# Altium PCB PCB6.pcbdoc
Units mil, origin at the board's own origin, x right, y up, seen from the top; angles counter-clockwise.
Board outline 4829.93 x 4826.48 mil, 2 copper layers (Top Layer, Bottom Layer); 46 components, 40 nets, 167 pads, 42 vias.
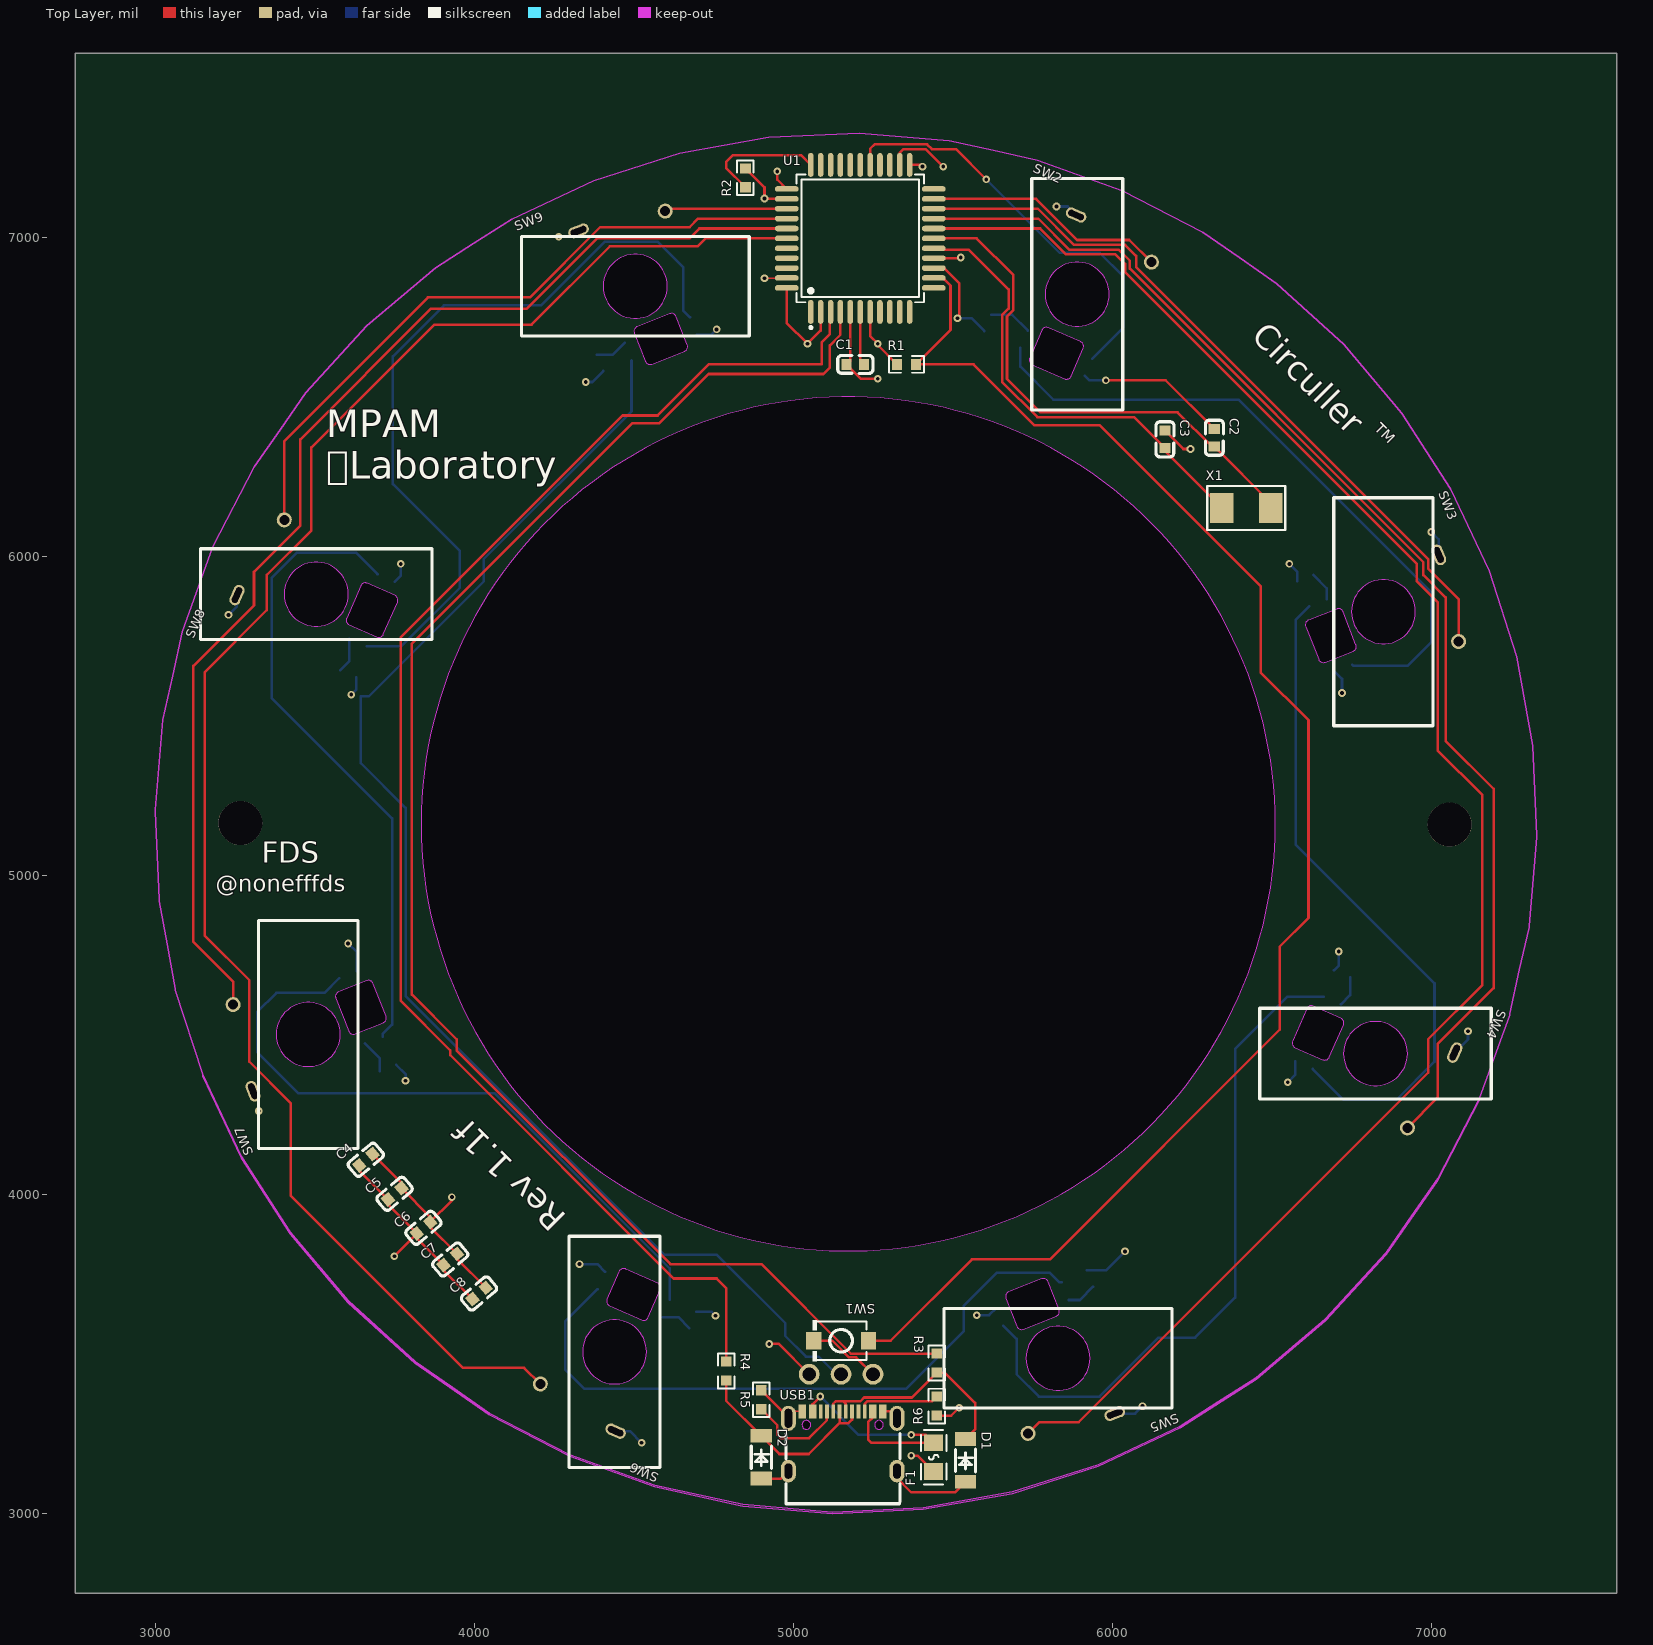
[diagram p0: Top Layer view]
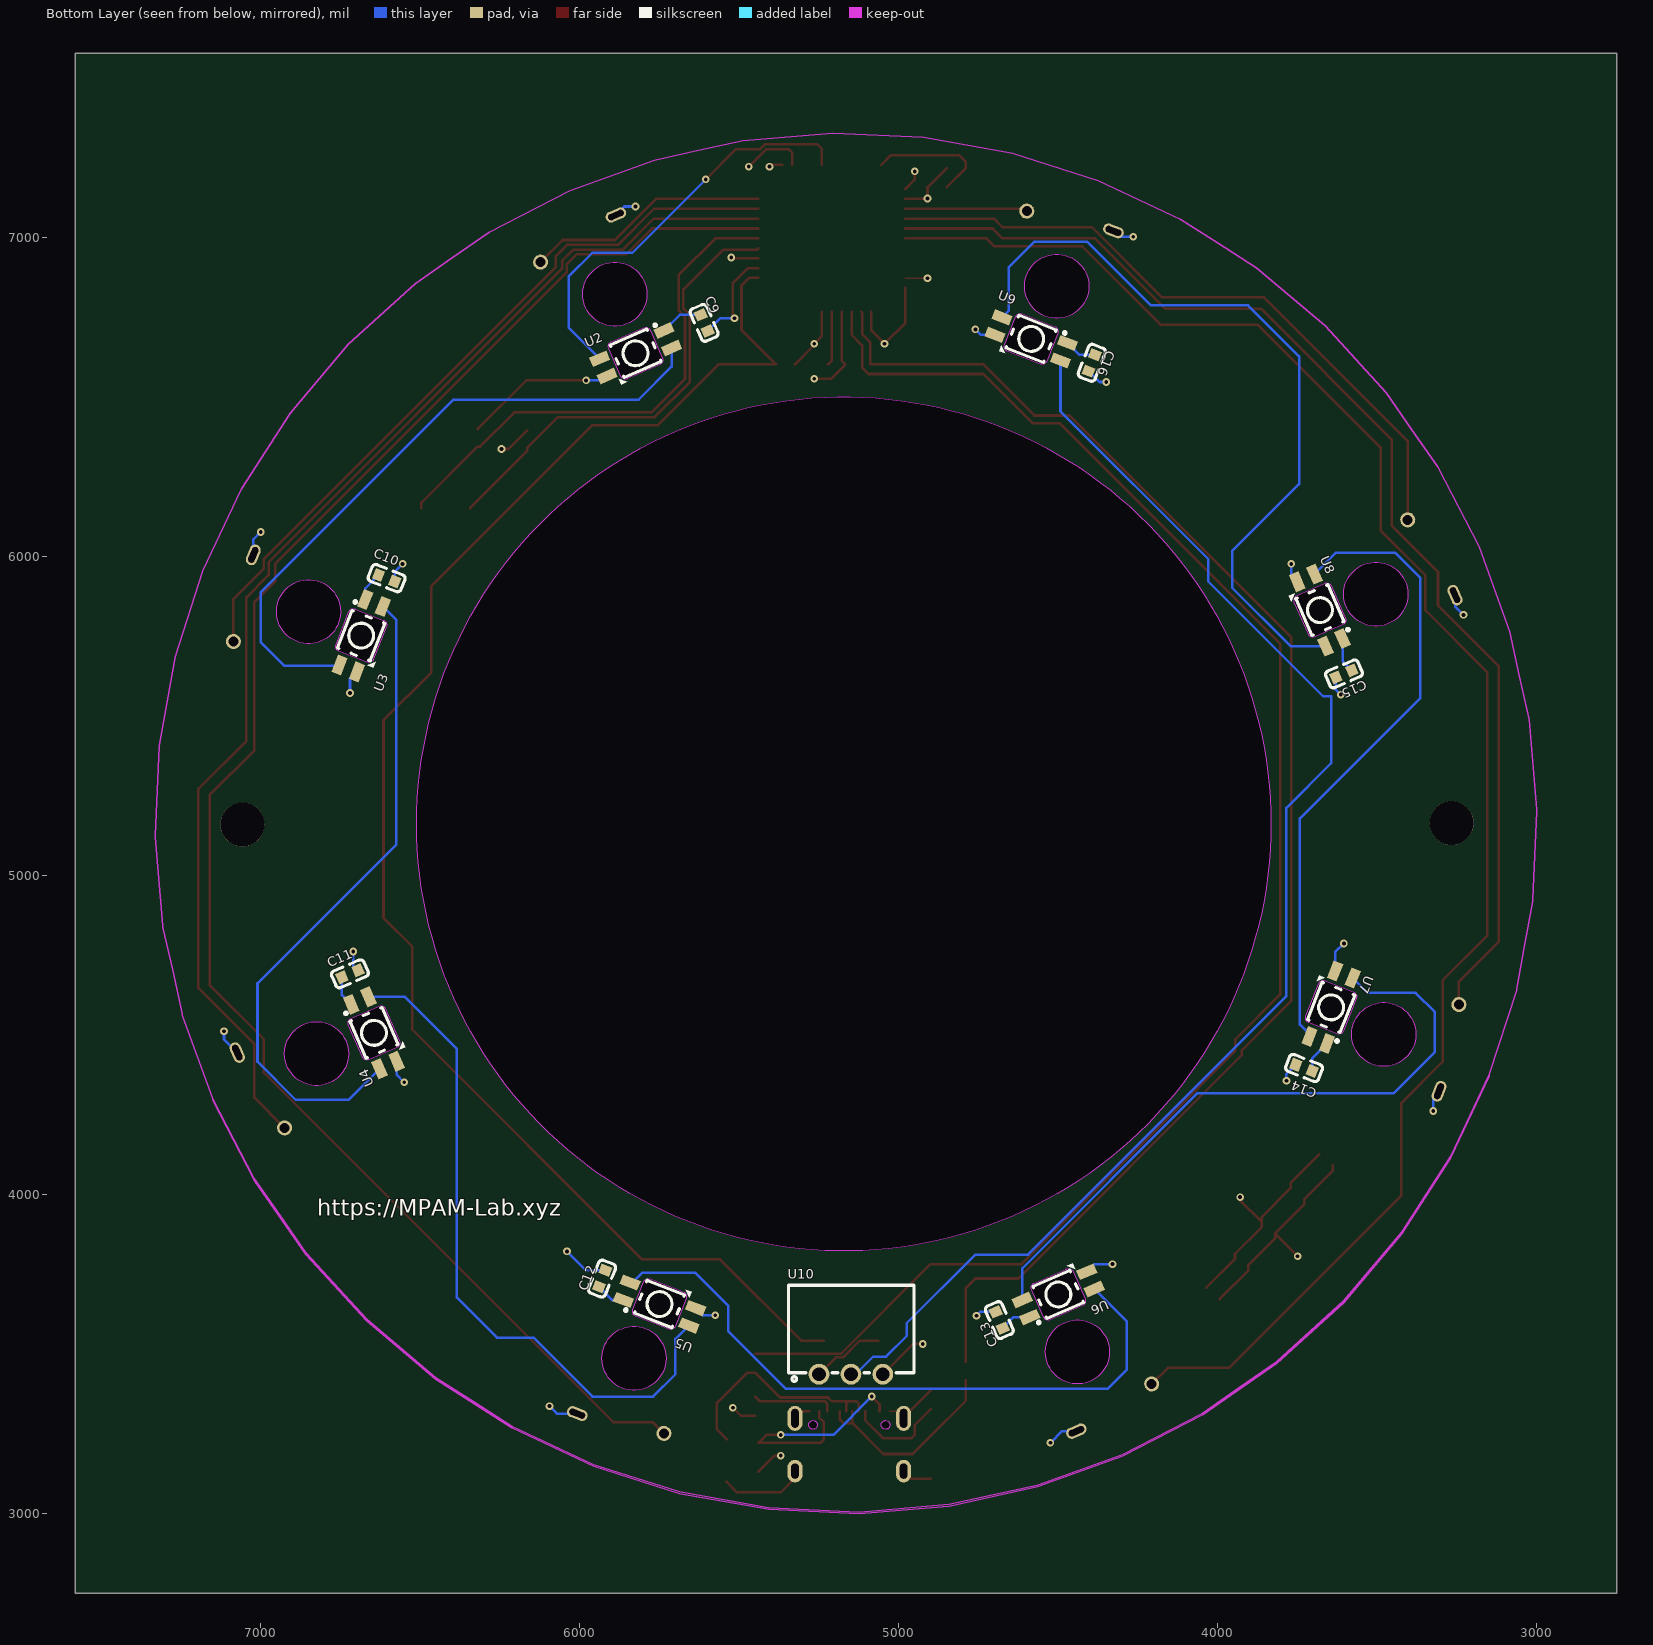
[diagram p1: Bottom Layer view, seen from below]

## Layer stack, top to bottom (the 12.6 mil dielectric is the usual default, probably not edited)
Top Layer: signal copper (thickness not stored)
Dielectric: dielectric 12.6, FR-4, Dk 4.8
Bottom Layer: signal copper (thickness not stored)

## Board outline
7579.93,2750 2750,2750 2750,7576.48 7579.93,7576.48
cut-out: 6510.41,5161.93 ccw(c5171.83,5161.93) 3833.24,5161.93 ccw(c5171.83,5161.93)

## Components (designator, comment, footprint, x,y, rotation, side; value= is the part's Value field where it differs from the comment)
C1 "CL10A105KB8NNNC" C0603 5194.52,6601.93 r0 top
C2 "CL10C220JB8NNNC" C0603 6319.52,6371.93 r270 top
C3 "CL10C220JB8NNNC" C0603 6164.52,6366.93 r270 top
C4 "CC0603KRX7R9BB104" C0603 3660.11,4109.3 r40.26 top
C5 "CC0603KRX7R9BB104" C0603 3750.42,4002.67 r40.26 top
C6 "CC0603KRX7R9BB104" C0603 3840.74,3896.03 r40.26 top
C7 "CC0603KRX7R9BB104" C0603 3924.76,3796.83 r40.26 top
C8 "CL10B474KA8NNNC" C0603 4015.07,3690.19 r40.26 top
C9 "CC0603KRX7R9BB104" C0603 5609.52,6731.93 r246.46 bottom
C10 "CC0603KRX7R9BB104" C0603 6604.52,5931.93 r201.46 bottom
C11 "CC0603KRX7R9BB104" C0603 6719.52,4691.93 r156.38 bottom
C12 "CC0603KRX7R9BB104" C0603 5929.52,3736.93 r111.38 bottom
C13 "CC0603KRX7R9BB104" C0603 4684.52,3606.93 r66.46 bottom
C14 "CC0603KRX7R9BB104" C0603 3729.52,4396.93 r21.46 bottom
C15 "CC0603KRX7R9BB104" C0603 3604.52,5631.93 r336.38 bottom
C16 "CC0603KRX7R9BB104" C0603 4394.52,6606.93 r291.38 bottom
D1 "ZMM3V6" LL-34_L3.5-W1.5-RD 5539.52,3166.93 r270 top
D2 "ZMM3V6" LL-34_L3.5-W1.5-RD 4899.52,3176.93 r270 top
F1 "2.5A/32VFUSESMD0805" F0805 5439.52,3176.93 r90 top
R1 "0603WAF1002T5E" R0603 5354.52,6601.93 r0 top
R2 "0603WAF1002T5E" R0603 4849.52,7186.93 r90 top
R3 "0603WAF220JT5E" R0603 5449.52,3471.93 r270 top
R4 "0603WAF220JT5E" R0603 4789.52,3446.93 r270 top
R5 "0603WAF5101T5E" R0603 4899.52,3356.93 r270 top
R6 "0603WAF5101T5E" R0603 5449.52,3336.93 r90 top
SW1 "TS-1088-AR02016" SW-SMD_L3.9-W3.0-P4.45 5149.52,3541.93 r180 top
SW2 "佳达隆矮轴_焊接" 佳达隆矮轴焊接#1 5889.52,6821.93 r336.46 top
SW3 "佳达隆矮轴_焊接" 佳达隆矮轴焊接#2 6849.52,5826.93 r291.46 top
SW4 "佳达隆矮轴_焊接" 佳达隆矮轴焊接#2 6824.52,4441.93 r246.38 top
SW5 "佳达隆矮轴_焊接" 佳达隆矮轴焊接#3 5829.52,3486.93 r201.38 top
SW6 "佳达隆矮轴_焊接" 佳达隆矮轴焊接#1 4439.52,3506.93 r156.46 top
SW7 "佳达隆矮轴_焊接" 佳达隆矮轴焊接#2 3479.52,4501.93 r111.46 top
SW8 "佳达隆矮轴_焊接" 佳达隆矮轴焊接#2 3504.52,5881.93 r66.38 top
SW9 "佳达隆矮轴_焊接" 佳达隆矮轴焊接#1 4504.52,6846.93 r21.38 top
U1 "ATMEGA32U4-AU" QFP-44_L10.0-W10.0-P0.80-LS13.2-BL 5209.52,6996.93 r0 top
U2 "WS2812B-3528幻彩反贴" LED-SMD_L3.2-W2.8-TR 5824.52,6636.93 r156.46 bottom
U3 "WS2812B-3528幻彩反贴" LED-SMD_L3.2-W2.8-TR 6684.52,5751.93 r111.46 bottom
U4 "WS2812B-3528幻彩反贴" LED-SMD_L3.2-W2.8-TR 6644.52,4506.93 r66.38 bottom
U5 "WS2812B-3528幻彩反贴" LED-SMD_L3.2-W2.8-TR 5749.52,3656.93 r21.38 bottom
U6 "WS2812B-3528幻彩反贴" LED-SMD_L3.2-W2.8-TR 4499.52,3686.93 r336.46 bottom
U7 "WS2812B-3528幻彩反贴" LED-SMD_L3.2-W2.8-TR 3644.52,4586.93 r291.46 bottom
U8 "WS2812B-3528幻彩反贴" LED-SMD_L3.2-W2.8-TR 3679.52,5831.93 r246.38 bottom
U9 "WS2812B-3528幻彩反贴" LED-SMD_L3.2-W2.8-TR 4584.52,6681.93 r201.38 bottom
U10 "XH2.54-WI-3P" CONN-TH_XH2.54-WI-3P 5149.52,3436.93 r180 bottom
USB1 "TYPE-C 16PIN 2MD(073)" USB-C-SMD_TYPE-C-6PIN-2MD-073 5154.52,3226.93 r0 top
X1 "XSHEELNANF-16MHZ" OSC-SMD_2P-L5.0-W3.2 6419.52,6151.93 r0 top

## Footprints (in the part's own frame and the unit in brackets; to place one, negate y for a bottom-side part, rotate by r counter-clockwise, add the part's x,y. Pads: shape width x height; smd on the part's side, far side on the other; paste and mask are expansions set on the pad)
C0603 [mm]
  rect 0.8x0.9 smd: 1(-0.7,0) 2(0.7,0)
  silkscreen extent -1.41,-0.71 1.39,0.72
CONN-TH_XH2.54-WI-3P [mm]
  round 1.65 hole 1.1: 1(-2.54,0) 2(0,0) 3(2.54,0)
  silkscreen extent -4.96,-0.56 5.02,7.09
F0805 [mm]
  rect 1.335x1.5 smd: 1(-1.142,0) 2(1.142,0)
  silkscreen extent -2.16,-1.02 2.16,1.02
LED-SMD_L3.2-W2.8-TR [mm]
  rect 1.5x0.82 smd: 1(2.8,0.75) 2(2.8,-0.75) 3(-2.8,-0.75) 4(-2.8,0.75)
  Multi-Layer board cut-out: 1.8,-1.2 1.746,-1.4 1.6,-1.547 1.4,-1.6 1.4,-1.6 1.4,-1.6 -1.4,-1.6 -1.403,-1.6 -1.406,-1.6 -1.406,-1.6 -1.604,-1.545 -1.747,-1.398 -1.8,-1.2 -1.8,-1.2 -1.8,-1.2 -1.8,-1.2 -1.8,-1.2 -1.8,-1.2 -1.8,1.2 -1.746,1.4 -1.6,1.546 -1.4,1.6 -1.4,1.6 1.4,1.6 1.4,1.6 1.6,1.547 1.746,1.4 1.8,1.2 1.8,1.2
  Multi-Layer keep-out region: 1.8,-1.2 1.746,-1.4 1.6,-1.547 1.4,-1.6 1.4,-1.6 1.4,-1.6 -1.4,-1.6 -1.403,-1.6 -1.406,-1.6 -1.406,-1.6 -1.604,-1.545 -1.747,-1.398 -1.8,-1.2 -1.8,-1.2 -1.8,-1.2 -1.8,-1.2 -1.8,-1.2 -1.8,-1.2 -1.8,1.2 -1.746,1.4 -1.6,1.546 -1.4,1.6 -1.4,1.6 1.4,1.6 1.4,1.6 1.6,1.547 1.746,1.4 1.8,1.2 1.8,1.2
  silkscreen extent -2.03,-1.83 2.42,1.52
LL-34_L3.5-W1.5-RD [mm]
  rect 1.1x1.7 smd: 1(-1.7,0) 2(1.7,0)
  silkscreen extent -0.9,-0.8 0.9,0.8
OSC-SMD_2P-L5.0-W3.2 [mm]
  rect 1.9x2.4 smd: 1(-1.95,0) 2(1.95,0)
  silkscreen extent -3.1,-1.75 3.1,1.75
QFP-44_L10.0-W10.0-P0.80-LS13.2-BL [mil]
  oval 17.36x74.62 smd: 1(-155,-230.37) 2(-124,-230.37) 3(-93,-230.37) 4(-62,-230.37) 5(-31,-230.37) 6(0,-230.37) 7(31,-230.37) 8(62,-230.37) 9(93,-230.37) 10(124,-230.37) 11(155,-230.37) 23(155,230.37) 24(124,230.37) 25(93,230.37) 26(62,230.37) 27(31,230.37) 28(0,230.37) 29(-31,230.37) 30(-62,230.37) 31(-93,230.37) 32(-124,230.37) 33(-155,230.37)
  oval 74.62x17.36 smd: 12(230.37,-155) 13(230.37,-124) 14(230.37,-93) 15(230.37,-62) 16(230.37,-31) 17(230.37,0) 18(230.37,31) 19(230.37,62) 20(230.37,93) 21(230.37,124) 22(230.37,155) 34(-230.37,155) 35(-230.37,124) 36(-230.37,93) 37(-230.37,62) 38(-230.37,31) 39(-230.37,0) 40(-230.37,-31) 41(-230.37,-62) 42(-230.37,-93) 43(-230.37,-124) 44(-230.37,-155)
  silkscreen extent -200,-283 200,200
R0603 [mil]
  rect 31.75x34.02 smd: 1(-29.66,0) 2(29.66,0)
  silkscreen extent -55,-26 55,26
SW-SMD_L3.9-W3.0-P4.45 [mm]
  rect 1.23x1.36 smd: 1(-2.185,0) 2(2.185,0)
  silkscreen extent -2.03,-1.62 2.25,1.62
USB-C-SMD_TYPE-C-6PIN-2MD-073 [mm]
  rect 0.6x1.1 smd: 1(-3.2,2.375) 2(-2.4,2.375) 11(2.4,2.375) 12(3.2,2.375)
  rect 0.3x1.1 smd: 3(-1.75,2.375) 4(-1.25,2.375) 5(-0.75,2.375) 6(-0.25,2.375) 7(0.25,2.375) 8(0.75,2.375) 9(1.25,2.375) 10(1.75,2.375)
  oval 1.2x1.8 hole 0.6 slot 1.2 at 90 deg: 13(-4.325,-2.375) 14(4.325,-2.375)
  oval 1.2x2 hole 0.6 slot 1.5 at 90 deg: 13(-4.325,1.825) 14(4.325,1.825)
  Multi-Layer board cut-out: -2.54,1.305 -2.575,1.457 -2.672,1.579 -2.812,1.646 -2.968,1.646 -3.108,1.579 -3.205,1.457 -3.24,1.305 -3.24,1.305 -3.205,1.153 -3.108,1.031 -2.968,0.964 -2.812,0.964 -2.672,1.031 -2.575,1.153 -2.54,1.305
  Multi-Layer board cut-out: 3.24,1.305 3.205,1.457 3.108,1.579 2.968,1.646 2.812,1.646 2.672,1.579 2.575,1.457 2.54,1.305 2.54,1.305 2.575,1.153 2.672,1.031 2.812,0.964 2.968,0.964 3.108,1.031 3.205,1.153 3.24,1.305
  Multi-Layer keep-out region: -2.54,1.305 -2.575,1.457 -2.672,1.579 -2.812,1.646 -2.968,1.646 -3.108,1.579 -3.205,1.457 -3.24,1.305 -3.24,1.305 -3.205,1.153 -3.108,1.031 -2.968,0.964 -2.812,0.964 -2.672,1.031 -2.575,1.153 -2.54,1.305
  Multi-Layer keep-out region: 3.24,1.305 3.205,1.457 3.108,1.579 2.968,1.646 2.812,1.646 2.672,1.579 2.575,1.457 2.54,1.305 2.54,1.305 2.575,1.153 2.672,1.031 2.812,0.964 2.968,0.964 3.108,1.031 3.205,1.153 3.24,1.305
  silkscreen extent -4.5,-4.97 4.57,0.6
佳达隆矮轴焊接#1 [mm]
  oval 1.7x0.9 hole 0.5 slot 1.3 at 0 deg: 1(-2.6,5.75)
  round 1.2 hole 0.8: 2(4.4,4.7)
  Multi-Layer board cut-out: 2.338,1.019 1.664,1.932 0.661,2.463 -0.473,2.506 -1.513,2.053 -2.254,1.193 -2.548,0.097 -2.338,-1.019 -2.338,-1.019 -1.664,-1.932 -0.661,-2.463 0.473,-2.506 1.513,-2.053 2.254,-1.193 2.548,-0.097 2.338,1.019
  Multi-Layer keep-out region: 2.338,1.019 1.664,1.932 0.661,2.463 -0.473,2.506 -1.513,2.053 -2.254,1.193 -2.548,0.097 -2.338,-1.019 -2.338,-1.019 -1.664,-1.932 -0.661,-2.463 0.473,-2.506 1.513,-2.053 2.254,-1.193 2.548,-0.097 2.338,1.019
  silkscreen extent -7,-9.89 7,9.89
佳达隆矮轴焊接#2 [mm]
  oval 1.7x0.9 hole 0.5 slot 1.3 at 0 deg: 1(-2.6,5.75)
  round 1.2 hole 0.8: 2(4.4,4.7)
  Multi-Layer board cut-out: 0.933,2.373 -0.189,2.543 -1.274,2.209 -2.106,1.437 -2.521,0.381 -2.437,-0.75 -1.87,-1.734 -0.933,-2.373 -0.933,-2.373 0.189,-2.543 1.274,-2.209 2.106,-1.437 2.521,-0.381 2.437,0.75 1.87,1.734 0.933,2.373
  Multi-Layer keep-out region: 0.933,2.373 -0.189,2.543 -1.274,2.209 -2.106,1.437 -2.521,0.381 -2.437,-0.75 -1.87,-1.734 -0.933,-2.373 -0.933,-2.373 0.189,-2.543 1.274,-2.209 2.106,-1.437 2.521,-0.381 2.437,0.75 1.87,1.734 0.933,2.373
  silkscreen extent -9.89,-7 9.89,7
佳达隆矮轴焊接#3 [mm]
  oval 1.7x0.9 hole 0.5 slot 1.3 at 180 deg: 1(-2.6,5.75)
  round 1.2 hole 0.8: 2(4.4,4.7)
  Multi-Layer board cut-out: -2.375,0.93 -2.543,-0.193 -2.207,-1.277 -1.435,-2.108 -0.378,-2.522 0.754,-2.436 1.736,-1.868 2.375,-0.93 2.375,-0.93 2.543,0.193 2.207,1.277 1.435,2.108 0.378,2.522 -0.754,2.436 -1.736,1.868 -2.375,0.93
  Multi-Layer keep-out region: -2.375,0.93 -2.543,-0.193 -2.207,-1.277 -1.435,-2.108 -0.378,-2.522 0.754,-2.436 1.736,-1.868 2.375,-0.93 2.375,-0.93 2.543,0.193 2.207,1.277 1.435,2.108 0.378,2.522 -0.754,2.436 -1.736,1.868 -2.375,0.93
  silkscreen extent -9.89,-7 9.89,7

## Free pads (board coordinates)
  round 137.8 hole 137.8 unplated: 13(3266.83,5164.52)
  round 137.8 hole 137.8: 14(7056.83,5159.52)

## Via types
v1: diameter 24.02, hole 12.01, Top Layer to Bottom Layer, 42 vias

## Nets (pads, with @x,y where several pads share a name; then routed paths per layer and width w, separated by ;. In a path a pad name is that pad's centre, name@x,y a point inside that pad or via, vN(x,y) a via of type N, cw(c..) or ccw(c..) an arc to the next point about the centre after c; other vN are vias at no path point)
1: SW9.2 U1.36 | length 383.9
  Top Layer w7.99: SW9.2 4605.91,7089.93 U1.36
2: SW5.2 U1.18 | length 5437
  Top Layer w7.99: U1.18 5773.52,7027.93 5854.52,6946.93 6009.52,6946.93 6039.52,6916.93 6039.52,6891.93 6954.52,5976.93 6954.52,5921.93 7019.52,5856.93 7019.52,5391.93 7159.52,5251.93 7159.52,4656.93 6989.52,4486.93 6989.52,4381.93 5894.52,3286.93 5771.12,3286.93 SW5.2
3: SW2.2 U1.21 | length 764.6
  Top Layer w7.99: U1.21 5760.52,7120.93 5889.52,6991.93 6052.68,6991.93 SW2.2
4: SW6.2 U1.39 | length 5383.4
  Top Layer w7.99: SW6.2 4156.35,3456.93 3964.52,3456.93 3424.52,3996.93 3424.52,4286.93 3294.52,4416.93 3294.52,4671.93 3154.52,4811.93 3154.52,5636.93 3349.52,5831.93 3349.52,5941.93 3489.52,6081.93 3489.52,6341.93 3874.52,6726.93 4179.52,6726.93 4424.52,6971.93 4699.52,6971.93 4724.52,6996.93 U1.39
5: SW3.2 U1.20 | length 2323.1
  Top Layer w7.99: U1.20 5766.52,7089.93 5879.52,6976.93 6039.52,6976.93 6074.52,6941.93 6074.52,6906.93 6989.52,5991.93 6989.52,5961.93 7085.1,5866.35 SW3.2
6: SW7.2 U1.38 | length 3760.2
  Top Layer w7.99: SW7.2 3243.94,4667.51 3119.52,4791.93 3119.52,5656.93 3309.52,5846.93 3309.52,5951.93 3454.52,6096.93 3454.52,6366.93 3864.52,6776.93 4164.52,6776.93 4384.52,6996.93 4674.52,6996.93 4705.52,7027.93 U1.38
7: SW4.2 U1.19 | length 3971.2
  Top Layer w7.99: U1.19 5767.52,7058.93 5864.52,6961.93 6019.52,6961.93 6054.52,6926.93 6054.52,6901.93 6974.52,5981.93 6974.52,5941.93 7044.52,5871.93 7044.52,5421.93 7194.52,5271.93 7194.52,4646.93 7019.52,4471.93 7019.52,4303.95 SW4.2
8: SW8.2 U1.37 | length 2110.5
  Top Layer w7.99: SW8.2 3404.4,6361.81 3854.52,6811.93 4174.52,6811.93 4394.52,7031.93 4674.52,7031.93 4701.52,7058.93 U1.37
$1N992: C2.2 U1.17 X1.2 | length 1634.3
  Top Layer w7.99: U1.17 5574.52,6996.93 5689.52,6881.93 5689.52,6771.93 5669.52,6751.93 5669.52,6556.93 5774.52,6451.93 6204.52,6451.93 6312.08,6344.37 C2.2 6496.29,6167.6 X1.2
$1N1040: C3.2 U1.16 X1.1 | length 1443.6
  Top Layer w7.99: U1.16 5443.89,6961.93 5549.52,6961.93 5674.52,6836.93 5674.52,6776.93 5654.52,6756.93 5654.52,6546.93 5764.52,6436.93 6066.96,6436.93 C3.2 6164.52,6330.16 X1.1
$1N1214: R1.2 SW1.1 U1.13 | length 4904.9
  Top Layer w7.99: SW1.1 5304.52,3541.93 5559.52,3796.93 5804.52,3796.93 6524.52,4516.93 6524.52,4776.93 6614.52,4866.93 6614.52,5486.93 6464.52,5636.93 6464.52,5906.93 5959.52,6411.93 5754.52,6411.93 5564.52,6601.93 R1.2 5492.51,6710.26 5492.51,6848.93 5468.52,6872.93 U1.13
$1N1318: R2.1 U1.33 | length 390.1
  Top Layer w7.99: R2.1 4789.52,7217.27 4789.52,7236.93 4809.52,7256.93 5024.89,7256.93 U1.33
$1N2823: F1.2 USB1.2 USB1.11 | length 775.4
  Top Layer w7.99: USB1.2 5060.03,3342.44 v1(5084.52,3366.93) ; USB1.11 5249.01,3301.42 5234.52,3286.93 5234.52,3231.93 5244.54,3221.91 F1.2 5414.5,3246.93 v1(5369.52,3246.93)
  Bottom Layer w7.99: v1(5084.52,3366.93) 5204.52,3246.93 v1(5369.52,3246.93)
$1N3423: D1.1 R3.2 USB1.5 USB1.7 | length 709
  Top Layer w7.99: USB1.5 5124.99,3344.39 5132.68,3352.08 5156.37,3352.08 ; USB1.7 5164.36,3344.09 5156.37,3352.08 ; D1.1 5569.52,3263.86 5569.52,3346.93 5474.18,3442.27 R3.2 5371.33,3364.08 5221.67,3364.08 5209.67,3352.08 5156.37,3352.08
$1N3438: D2.1 R4.2 USB1.6 USB1.8 | length 634.4
  Top Layer w7.99: R4.2 4789.52,3353.86 D2.1 4956.45,3186.93 5048.18,3186.93 5144.67,3283.43 ; USB1.6 5144.67,3283.43 ; USB1.8 5184.04,3294.78 5172.68,3283.43 5144.67,3283.43
$1N3472: R5.2 USB1.4 | length 311.8
  Top Layer w7.99: R5.2 4949.52,3277.27 4949.52,3246.93 4959.52,3236.93 5049.52,3236.93 5105.31,3292.72 USB1.4
$1N3479: R6.2 USB1.10 | length 259.1
  Top Layer w7.99: USB1.10 5223.42,3344.09 5231.41,3352.08 5435.01,3352.08 R6.2
$1N3933: U2.2 U3.4 | length 2074.7
  Bottom Layer w7.99: U2.2 5711.66,6594.79 5814.52,6491.93 6394.52,6491.93 6999.52,5886.93 6999.52,5731.93 6924.52,5656.93 6755.52,5656.93 U3.4
$1N3938: U3.2 U4.4 | length 2096.5
  Bottom Layer w7.99: U3.2 6574.52,5801.53 6574.52,5096.93 7009.52,4661.93 7009.52,4416.93 6889.52,4296.93 6724.56,4296.93 U4.4
$1N3943: U4.2 U5.4 | length 2136.6
  Bottom Layer w7.99: U5.4 5699.52,3547.35 5699.52,3436.93 5769.52,3366.93 5959.52,3366.93 6144.52,3551.93 6259.52,3551.93 6384.52,3676.93 6384.52,4456.93 6547.35,4619.76 U4.2
$1N3948: U5.2 U6.4 | length 2086.3
  Bottom Layer w7.99: U6.4 4284.52,3601.75 4284.52,3451.93 4345.71,3390.74 5353.33,3390.74 5534.52,3571.93 5534.52,3651.93 5637,3754.41 5804.03,3754.41 5833.82,3724.61 U5.2
$1N3953: U6.2 U7.4 | length 2099.2
  Bottom Layer w7.99: U7.4 3529.91,4631.93 3379.52,4631.93 3319.52,4571.93 3319.52,4446.93 3449.52,4316.93 4064.52,4316.93 4612.38,3769.07 U6.2
$1N3959: U7.2 U8.4 | length 1998.6
  Bottom Layer w7.99: U8.4 3629.47,6011.93 3444.52,6011.93 3364.52,5931.93 3364.52,5556.93 3742.14,5179.3 3742.14,4532.51 3712.32,4502.69 U7.2
$1N3965: U8.2 U9.4 | length 2438.5
  Bottom Layer w7.99: U8.2 3771.68,5719.09 3954.52,5901.93 3954.52,6016.93 3744.52,6226.93 3744.52,6626.93 3904.52,6786.93 4209.52,6786.93 4409.52,6986.93 4574.52,6986.93 4654.52,6906.93 4654.52,6771.5 U9.4
$1N4279: C9.1 U2.1 | length 135.1
  Bottom Layer w7.99: C9.1 5686.09,6757.19 U2.1
$1N4296: C10.1 U3.1 | length 93.9
  Bottom Layer w7.99: C10.1 6671.68,5900.5 U3.1
$1N4306: C11.1 U4.1 | length 96.8
  Bottom Layer w7.99: U4.1 6744.77,4625.12 C11.1
$1N4316: C12.1 U5.1 | length 93.9
  Bottom Layer w7.99: U5.1 5897.92,3669.62 C12.1
$1N4320: C13.1 U6.1 | length 98.9
  Bottom Layer w7.99: U6.1 4639.35,3615.82 C13.1
$1N4353: C16.1 U9.1 | length 101.8
  Bottom Layer w7.99: C16.1 4434.45,6632.59 U9.1
$1N4416: C14.1 U7.1 | length 105.9
  Bottom Layer w7.99: U7.1 3703.87,4427.02 C14.1
$1N4551: C15.1 U8.1 | length 111.8
  Bottom Layer w7.99: C15.1 3608.29,5671.99 U8.1
$1N4867: C1.2 U1.6 | length 169.8
  Top Layer w7.99: U1.6 5209.52,6614.49 C1.2
D+: R4.1 U1.3 | length 4621.9
  Top Layer w7.99: R4.1 4789.52,3706.93 4759.52,3736.93 4624.52,3736.93 3924.52,4436.93 3924.52,4451.93 3769.52,4606.93 3769.52,5746.93 4464.52,6441.93 4574.52,6441.93 4734.52,6601.93 5089.52,6601.93 5089.52,6671.93 5114.52,6696.93 5114.52,6764.56 U1.3
D-: R3.1 U1.4 | length 5088.2
  Top Layer w7.99: U1.4 5147.52,6694.93 5114.52,6661.93 5114.52,6591.93 5094.52,6571.93 4734.52,6571.93 4579.52,6416.93 4494.52,6416.93 3804.52,5726.93 3804.52,4626.93 3944.52,4486.93 3944.52,4451.93 4614.52,3781.93 4899.52,3781.93 5179.86,3501.59 R3.1
DOUT: U9.2 U10.2 | length 4295.5
  Bottom Layer w7.99: U9.2 4492.63,6455.04 4029.52,5991.93 4029.52,5921.93 3669.52,5561.93 3644.52,5561.93 3644.52,5351.93 3784.52,5211.93 3784.52,4621.93 4594.52,3811.93 4759.52,3811.93 4974.52,3596.93 4974.52,3556.93 5039.52,3491.93 5079.52,3491.93 5134.52,3436.93 U10.2
GND: C1.1 C2.1 C3.1 C4.1 C5.1 C6.1 C7.1 C8.1 D1.2 D2.2 R2.2 R5.1 R6.1 SW1.2 SW2.1 SW3.1 SW4.1 SW5.1 SW6.1 SW7.1 SW8.1 SW9.1 U1.5 U1.15 U1.23 U1.35 U1.43 U2.3 U3.3 U4.3 U5.3 U6.3 U7.3 U8.3 U9.3 U10.1 USB1.1 USB1.12 USB1.13 USB1.14 | length 4007.4
  Top Layer w5: v1(4909.52,6871.93) 4978.15,6871.93 U1.43 ; USB1.13@4984.24,3298.78 5005.89,3320.43 USB1.1
  Top Layer w7.99: C4.1 3639.07,4075.17 C5.1 3729.39,3968.53 C6.1 ; v1(3749.52,3806.93) 3749.52,3808.03 C6.1 ; C8.1 3903.72,3762.69 C7.1 3819.71,3863.03 C6.1 ; R2.2 4909.52,7156.59 v1(4909.52,7121.93) 4910.52,7120.93 U1.35 ; D2.2 4960.82,3110 USB1.13@4984.24,3133.42 ; R5.1 4984.24,3301.86 USB1.13@4984.24,3298.78 ; SW1.2 5122.54,3541.93 5174.88,3489.58 5196.87,3489.58 U10.1 ; U1.5 5178.52,6613.49 C1.1 5211.96,6556.93 v1(5264.52,6556.93) ; USB1.12 5303.14,3320.43 USB1.14@5324.79,3298.78 ; USB1.14@5324.79,3133.42 5324.79,3111.65 5369.52,3066.93 5506.45,3066.93 D1.2 ; U1.23 5399.15,7227.3 v1(5404.52,7221.93) ; U1.15 5522.52,6934.93 v1(5524.52,6936.93) ; R6.1 5494.86,3307.27 v1(5519.52,3331.93) ; v1(5979.52,6551.93) 6167.08,6551.93 C2.1 ; C3.1 6222.08,6336.93 v1(6244.52,6336.93)
  Bottom Layer w7.99: v1(3229.52,5816.93) 3256.09,5843.5 SW8.1 ; SW7.1 3324.52,4305.61 v1(3324.52,4261.93) ; v1(3604.52,4786.93) 3631.68,4759.77 U7.3 ; U8.3 3769.52,5939.87 v1(3769.52,5976.93) ; v1(4264.52,7001.93) 4308.19,7001.93 SW9.1 ; v1(4329.52,3781.93) 4386.35,3781.93 U6.3 ; SW6.1 4487.94,3258.51 v1(4524.52,3221.93) ; U9.3 4742.21,6694.62 v1(4759.52,6711.93) ; v1(5574.52,3621.93) 5613.79,3621.93 U5.3 ; v1(5824.52,7096.93) 5859.52,7096.93 SW2.1 ; U2.3 5927.68,6551.93 v1(5979.52,6551.93) ; SW5.1 6071.04,3313.45 v1(6094.52,3336.93) ; v1(6549.52,4351.93) 6573.29,4375.7 U4.3 ; U3.3 6719.52,5616.37 v1(6719.52,5571.93) ; v1(6999.52,6076.93) 7022.77,6053.68 SW3.1 ; SW4.1 7114.52,4486.57 v1(7114.52,4511.93)
LED: U1.27 U2.4 | length 1319.5
  Top Layer w7.99: U1.27 5240.52,7277.93 5254.52,7291.93 5419.52,7291.93 5434.52,7276.93 5509.52,7276.93 v1(5604.52,7181.93)
  Bottom Layer w7.99: v1(5604.52,7181.93) 5834.52,6951.93 5959.52,6951.93 6034.52,6876.93 6034.52,6717.11 U2.4
VCC: C4.2 C5.2 C6.2 C7.2 C8.2 C9.2 C10.2 C11.2 C12.2 C13.2 C14.2 C15.2 C16.2 F1.1 R1.1 U1.2 U1.7 U1.14 U1.24 U1.34 U1.44 U10.3 | length 2559.1
  Top Layer w7.99: C4.2 3771.45,4036.8 C5.2 3861.77,3930.16 C6.2 ; v1(3929.61,3991.93) 3929.61,3981.68 C6.2 ; C8.2 3945.79,3798.32 C7.2 3861.77,3898.66 C6.2 ; v1(4924.52,3531.93) 4954.52,3531.93 U10.3 ; v1(4949.52,7206.93) 4949.52,7181.56 U1.34 ; U1.44 4979.15,6732.3 v1(5044.52,6666.93) 5085.52,6707.93 U1.2 ; U1.7 5240.52,6690.93 v1(5264.52,6666.93) 5264.52,6662.27 R1.1 ; U1.24 5333.52,7265.93 5344.52,7276.93 5414.52,7276.93 v1(5469.52,7221.93) ; v1(5369.52,3181.93) 5389.54,3181.93 F1.1 ; U1.14 5472.52,6903.93 5519.52,6856.93 5519.52,6751.93 v1(5514.52,6746.93)
  Bottom Layer w7.99: v1(3614.52,5566.93) 3629.77,5582.18 C15.2 ; C14.2 3784.52,4377.66 v1(3784.52,4356.93) ; v1(4349.52,6546.93) 4370.23,6546.93 C16.2 ; C13.2 4744.24,3632.19 v1(4756.12,3620.32) ; v1(5514.52,6746.93) 5558.24,6746.93 C9.2 ; C12.2 5980.18,3762.59 v1(6039.52,3821.93) ; v1(6554.52,5976.93) 6578.87,5952.58 C10.2 ; C11.2 6709.52,4718.22 v1(6709.52,4761.93)
"": pad.13 pad.14 U1.1 U1.8 U1.9 U1.10 U1.11 U1.12 U1.22 U1.25 U1.26 U1.28 U1.29 U1.30 U1.31 U1.32 U1.40 U1.41 U1.42 USB1.3 USB1.9

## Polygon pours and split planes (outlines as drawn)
GND on GND (split plane): 5405.87,3028.1 5124.25,3015 4843.34,3038.7 4705.63,3068.75 4567.92,3098.8 4302.72,3194.26 4052.28,3323.46 3936.58,3403.81 3820.87,3484.17 3612.47,3673.66 3430.62,3888.67 3354.54,4007.1 3278.46,4125.53 3158.56,4380.22 3073.28,4642.57 3073.28,4645.86 ccw(c3072.48,4646.68) 3073.12,4647.64 3048.12,4786.77 ccw(c3047.18,4786.61) 3048.12,4786.8 ccw(c3047.17,4786.64) 3048.11,4786.83 3023.28,4920.16 3023.28,4924.11 ccw(c3022.29,4924.33) 3023.27,4924.59 3010.1,5201.86 3010.1,5206.08 3033.87,5486.68 3063.97,5624.12 3094.08,5761.56 3189.72,6026.24 3319.16,6276.2 3399.68,6391.68 3480.19,6507.16 3670.04,6715.17 3885.47,6896.66 4004.13,6972.6 4122.79,7048.54 4377.94,7168.2 4646.57,7253.59 4785.31,7278.43 4924.06,7303.27 5205.67,7316.36 5486.59,7292.66 5624.3,7262.61 5762,7232.56 6027.2,7137.1 6277.65,7007.91 6393.35,6927.55 6509.05,6847.19 6717.46,6657.71 6899.3,6442.69 6975.39,6324.26 7051.47,6205.83 7171.36,5951.17 7256.92,5683.07 7281.8,5544.59 7306.69,5406.12 7319.83,5124.62 7319.83,5120.41 7296,4844.04 ccw(c7296.93,4843.56) 7295.97,4843.17 7295.97,4839.42 7265.97,4707.32 ccw(c7266.9,4707.09) 7265.96,4707.28 ccw(c7266.89,4707.05) 7265.95,4707.24 7235.71,4569.16 ccw(c7236.17,4568.01) 7235.47,4566.99 7235.47,4563.91 7140.22,4305.15 7010.76,4055.16 6930.25,3939.68 6849.74,3824.2 6659.89,3616.2 6444.46,3434.7 6325.8,3358.76 6207.14,3282.83 5951.98,3163.17 5683.36,3077.77 5544.62,3052.93
GND on GND (split plane): 3258.1,5883.44 3283.67,5872.25 3279.67,5863.09 3254.09,5874.27
GND on GND (split plane): 3232.52,5894.62 3258.1,5883.44 3254.09,5874.27 3228.51,5885.46
GND on GND (split plane): 3234.01,5840.85 3251.51,5880.86 3260.67,5876.85 3243.18,5836.85
GND on GND (split plane): 3251.51,5880.86 3269.01,5920.87 3278.17,5916.86 3260.67,5876.85
GND on GND (split plane): 3304.44,4328.51 3330.42,4338.72 3334.08,4329.41 3308.1,4319.2
GND on GND (split plane): 3278.46,4318.3 3304.44,4328.51 3308.1,4319.2 3282.12,4308.99
GND on GND (split plane): 3310.92,4325.69 3326.89,4285.05 3317.59,4281.39 3301.61,4322.03
GND on GND (split plane): 3294.95,4366.32 3310.92,4325.69 3301.61,4322.03 3285.64,4362.67
GND on GND (split plane): 4331.33,7022.23 4341.51,6996.24 4332.19,6992.59 4322.02,7018.59
GND on GND (split plane): 4321.15,7048.23 4331.33,7022.23 4322.02,7018.59 4311.84,7044.58
GND on GND (split plane): 4284.19,7009.15 4324.85,7025.07 4328.5,7015.75 4287.84,6999.84
GND on GND (split plane): 4324.85,7025.07 4365.51,7040.98 4369.15,7031.67 4328.5,7015.75
GND on GND (split plane): 4438.36,3260.5 4449.51,3286.1 4458.67,3282.1 4447.52,3256.51
GND on GND (split plane): 4427.21,3234.91 4438.36,3260.5 4447.52,3256.51 4436.37,3230.92
GND on GND (split plane): 4444.94,3263.09 4484.97,3245.65 4480.97,3236.48 4440.94,3253.92
GND on GND (split plane): 4404.91,3280.53 4444.94,3263.09 4440.94,3253.92 4400.91,3271.36
GND on GND (split plane): 4950.42,3138.42 4984.24,3138.42 4984.24,3128.42 4950.42,3128.42
GND on GND (split plane): 4984.24,3138.42 5018.06,3138.42 5018.06,3128.42 4984.24,3128.42
GND on GND (split plane): 4979.24,3133.42 4979.24,3179.06 4989.24,3179.06 4989.24,3133.42
GND on GND (split plane): 4989.24,3133.42 4989.24,3087.79 4979.24,3087.79 4979.24,3133.42
GND on GND (split plane): 4950.42,3303.78 4984.24,3303.78 4984.24,3293.78 4950.42,3293.78
GND on GND (split plane): 4984.24,3303.78 5018.06,3303.78 5018.06,3293.78 4984.24,3293.78
GND on GND (split plane): 4979.24,3298.78 4979.24,3348.35 4989.24,3348.35 4989.24,3298.78
GND on GND (split plane): 4989.24,3298.78 4989.24,3249.21 4979.24,3249.21 4979.24,3298.78
GND on GND (split plane): 5249.52,3441.93 5292.2,3441.93 5292.2,3431.93 5249.52,3431.93
GND on GND (split plane): 5206.84,3441.93 5249.52,3441.93 5249.52,3431.93 5206.84,3431.93
GND on GND (split plane): 5254.52,3436.93 5254.52,3394.25 5244.52,3394.25 5244.52,3436.93
GND on GND (split plane): 5244.52,3436.93 5244.52,3479.61 5254.52,3479.61 5254.52,3436.93
GND on GND (split plane): 5290.97,3138.42 5324.79,3138.42 5324.79,3128.42 5290.97,3128.42
GND on GND (split plane): 5324.79,3138.42 5358.61,3138.42 5358.61,3128.42 5324.79,3128.42
GND on GND (split plane): 5319.79,3133.42 5319.79,3179.06 5329.79,3179.06 5329.79,3133.42
GND on GND (split plane): 5329.79,3133.42 5329.79,3087.79 5319.79,3087.79 5319.79,3133.42
GND on GND (split plane): 5290.97,3303.78 5324.79,3303.78 5324.79,3293.78 5290.97,3293.78
GND on GND (split plane): 5324.79,3303.78 5358.61,3303.78 5358.61,3293.78 5324.79,3293.78
GND on GND (split plane): 5319.79,3298.78 5319.79,3348.35 5329.79,3348.35 5329.79,3298.78
GND on GND (split plane): 5329.79,3298.78 5329.79,3249.21 5319.79,3249.21 5319.79,3298.78
GND on GND (split plane): 5870.36,7046.75 5881.51,7072.35 5890.68,7068.35 5879.53,7042.76
GND on GND (split plane): 5881.51,7072.35 5892.66,7097.94 5901.83,7093.95 5890.68,7068.35
GND on GND (split plane): 5848.06,7092.37 5888.09,7074.93 5884.1,7065.77 5844.07,7083.21
GND on GND (split plane): 5888.09,7074.93 5928.12,7057.49 5924.13,7048.33 5884.1,7065.77
GND on GND (split plane): 6001.84,3341.26 6012.02,3315.27 6002.71,3311.62 5992.53,3337.62
GND on GND (split plane): 6012.02,3315.27 6022.2,3289.27 6012.88,3285.63 6002.71,3311.62
GND on GND (split plane): 6005.54,3318.1 6046.2,3334.02 6049.85,3324.71 6009.19,3308.79
GND on GND (split plane): 5964.88,3302.18 6005.54,3318.1 6009.19,3308.79 5968.53,3292.87
GND on GND (split plane): 6994.96,5999.44 7020.94,6009.65 7024.6,6000.35 6998.61,5990.14
GND on GND (split plane): 7020.94,6009.65 7046.92,6019.86 7050.58,6010.56 7024.6,6000.35
GND on GND (split plane): 7011.45,6047.47 7027.42,6006.83 7018.11,6003.17 7002.14,6043.81
GND on GND (split plane): 7027.42,6006.83 7043.39,5966.19 7034.09,5962.53 7018.11,6003.17
GND on GND (split plane): 7049.37,4460.77 7074.95,4449.58 7070.94,4440.42 7045.36,4451.61
GND on GND (split plane): 7074.95,4449.58 7100.52,4438.4 7096.52,4429.23 7070.94,4440.42
GND on GND (split plane): 7068.36,4447 7085.86,4487.01 7095.02,4483 7077.53,4443
GND on GND (split plane): 7050.87,4407 7068.36,4447 7077.53,4443 7060.03,4402.99
VCC on VCC (split plane): 5405.87,3028.1 5124.25,3015 4843.34,3038.7 4705.63,3068.75 4567.92,3098.8 4302.72,3194.26 4052.28,3323.46 3936.58,3403.81 3820.87,3484.17 3612.47,3673.66 3430.62,3888.67 3354.54,4007.1 3278.46,4125.53 3158.56,4380.22 3073.28,4642.57 3073.28,4645.86 ccw(c3072.48,4646.68) 3073.12,4647.64 3048.12,4786.77 ccw(c3047.18,4786.61) 3048.12,4786.8 ccw(c3047.17,4786.64) 3048.11,4786.83 3023.28,4920.16 3023.28,4924.11 ccw(c3022.29,4924.33) 3023.27,4924.59 3010.1,5201.86 3010.1,5206.08 3033.87,5486.68 3063.97,5624.12 3094.08,5761.56 3189.72,6026.24 3319.16,6276.2 3399.68,6391.68 3480.19,6507.16 3670.04,6715.17 3885.47,6896.66 4004.13,6972.6 4122.79,7048.54 4377.94,7168.2 4646.57,7253.59 4785.31,7278.43 4924.06,7303.27 5205.67,7316.36 5486.59,7292.66 5624.3,7262.61 5762,7232.56 6027.2,7137.1 6277.65,7007.91 6393.35,6927.55 6509.05,6847.19 6717.46,6657.71 6899.3,6442.69 6975.39,6324.26 7051.47,6205.83 7171.36,5951.17 7256.92,5683.07 7281.8,5544.59 7306.69,5406.12 7319.83,5124.62 7319.83,5120.41 7296,4844.04 ccw(c7296.93,4843.56) 7295.97,4843.17 7295.97,4839.42 7265.97,4707.32 ccw(c7266.9,4707.09) 7265.96,4707.28 ccw(c7266.89,4707.05) 7265.95,4707.24 7235.71,4569.16 ccw(c7236.17,4568.01) 7235.47,4566.99 7235.47,4563.91 7140.22,4305.15 7010.76,4055.16 6930.25,3939.68 6849.74,3824.2 6659.89,3616.2 6444.46,3434.7 6325.8,3358.76 6207.14,3282.83 5951.98,3163.17 5683.36,3077.77 5544.62,3052.93
VCC on VCC (split plane): 5049.52,3441.93 5092.2,3441.93 5092.2,3431.93 5049.52,3431.93
VCC on VCC (split plane): 5006.84,3441.93 5049.52,3441.93 5049.52,3431.93 5006.84,3431.93
VCC on VCC (split plane): 5054.52,3436.93 5054.52,3394.25 5044.52,3394.25 5044.52,3436.93
VCC on VCC (split plane): 5044.52,3436.93 5044.52,3479.61 5054.52,3479.61 5054.52,3436.93

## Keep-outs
Board Outline Layer:
  lines w3.94 net "": 3149.15,4376.49 3063.18,4640.97 3063.18,4645.86 3038.18,4784.98 3013.18,4919.23 3013.18,4924.11 3000,5201.62 3000,5206.5 3023.86,5488.19 3054.11,5626.28 3084.35,5764.37 3180.45,6030.3 3310.5,6281.43 3391.39,6397.46 3472.28,6513.48 3663.02,6722.46 3879.47,6904.81 3998.68,6981.11 4117.9,7057.4 4374.25,7177.62 4644.14,7263.42 4783.53,7288.37 4922.93,7313.32 5205.86,7326.48 5488.1,7302.67 5626.45,7272.48 5764.8,7242.29 6031.25,7146.38 6282.87,7016.58 6399.11,6935.84 6515.36,6855.11 6724.74,6664.73 6907.44,6448.71 6983.89,6329.72 7060.33,6210.73 7180.78,5954.87 7266.74,5685.51 7291.74,5546.38 7316.74,5407.25 7329.93,5124.86 7329.93,5119.98 7306.07,4843.17 7306.07,4838.29 7275.82,4705.08 7245.57,4566.99 7245.57,4562.11 7149.48,4301.06 ; 3149.15,4376.49 3269.6,4120.63 3346.04,4001.64 3422.48,3882.65 3605.18,3666.63 3814.57,3476.25 3930.82,3395.52 4047.06,3314.78 4298.68,3184.98 4565.12,3089.07 4703.48,3058.88 4841.83,3028.69 5124.06,3004.88 5407,3018.04 5546.39,3042.99 5685.79,3067.94 5955.67,3153.74 6212.03,3273.96 6331.24,3350.26 6450.46,3426.55 6666.9,3608.9 6857.65,3817.88 6938.54,3933.91 7019.43,4049.93 7149.48,4301.06 ; 3149.15,4376.49 3149.15,4371.61 3269.6,4115.75 3422.48,3877.77 3605.18,3661.75 3814.57,3471.37 4047.06,3309.9 4298.68,3180.1 4565.12,3084.19 4841.83,3023.81 5124.06,3000 5407,3013.16 5685.79,3063.06 5955.67,3148.86 6212.03,3269.08 6450.46,3421.67 6666.9,3604.02 6857.65,3813 7019.43,4045.05 7149.48,4296.18 7149.48,4301.06
Multi-Layer:
  region net "": 6510.41,5161.93 ccw(c5171.83,5161.93) 3833.24,5161.93 ccw(c5171.83,5161.93)

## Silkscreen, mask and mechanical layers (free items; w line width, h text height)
Top Silkscreen Layer:
  text "Circuller" at 6431.88,6687.84 h76.65 r315
  text "TM" at 6819.31,6399.4 h33.22 r315
  text "MPAM  /  Laboratory" at 3535.69,6243.57 h86.82
  text "FDS" at 3333.85,5039.65 h66.43
  text "@nonefffds" at 3189.45,4949.41 h51.1
  text "Rev 1.1f" at 4292.51,3931.86 h76.65 r135
Bottom Silkscreen Layer:
  text "https://MPAM-Lab.xyz" at 6822,3934.41 h51.1
Mechanical Layer:
  circle w1 net "": c5171.83,5161.93 r1338.58
Mech6:
  lines w3.94 net "": 3096.29,4672.37 3311.94,4123.66 3861.7,4338.89 3646.06,4887.6 3096.29,4672.37 ; 3116.43,5736.63 3352.69,6276.82 3893.92,6041.01 3657.66,5500.82 3116.43,5736.63 ; 4051.69,3356.9 4287.95,3897.09 4829.18,3661.29 4592.92,3121.1 4051.69,3356.9 ; 4120.93,7015.15 4670.7,7230.38 4886.35,6681.67 4336.58,6466.43 4120.93,7015.15 ; 5443.58,3649.71 5993.34,3864.94 6208.99,3316.23 5659.22,3100.99 5443.58,3649.71 ; 5500.75,6670.08 6041.98,6434.28 6278.24,6974.47 5737.01,7210.27 5500.75,6670.08 ; 6436.01,4290.35 6977.24,4054.55 7213.49,4594.74 6672.26,4830.54 6436.01,4290.35 ; 6468.22,5992.47 6683.87,5443.76 7233.64,5659 7017.99,6207.71 6468.22,5992.47
Mech15:
  lines w3.94 net "": 3826.62,5190.92 3841.37,5360.17 3841.37,5365.05 3860.07,5450.42 3878.77,5530.9 3878.77,5535.78 3938.17,5695.29 4018.57,5850.54 4118.58,5993.99 4236.49,6123.18 4370.29,6235.9 4517.69,6330.23 4676.16,6404.55 4843,6457.58 5015.34,6488.43 5190.25,6496.57 5364.72,6481.85 5535.77,6444.52 5700.48,6385.23 5856.03,6304.99 5999.75,6205.17 6129.19,6087.49 6242.13,5953.94 6336.64,5806.83 6411.11,5648.66 6464.25,5487.03 6464.25,5482.15 6479.7,5401.02 6495.16,5315.02 6495.16,5310.13 6503.3,5140.45 6488.56,4966.31 6469.86,4880.95 6451.16,4795.58 6391.75,4631.19 6311.36,4475.94 6261.35,4404.22 6211.35,4332.5 6093.44,4203.31 5959.64,4090.58 5885.94,4043.42 5812.24,3996.26 5653.77,3921.94 5486.93,3868.9 5400.76,3853.47 5314.59,3838.05 5139.68,3829.91 4965.21,3844.64 4879.68,3863.3 4794.15,3881.96 4629.44,3941.25 4473.9,4021.49 4402.04,4071.4 4330.17,4121.31 4200.74,4238.99 4087.79,4372.54 4040.54,4446.09 3993.28,4519.65 3918.82,4677.82 3865.68,4844.33 3850.23,4930.34 3834.77,5016.35 3826.62,5190.92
